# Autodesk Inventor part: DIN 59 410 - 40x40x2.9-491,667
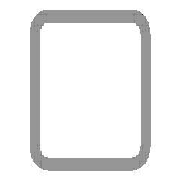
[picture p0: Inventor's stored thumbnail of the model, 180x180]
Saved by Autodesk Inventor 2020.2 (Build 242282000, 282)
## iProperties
Manager: www.cadconsulting.pl
Company: Fabian Stasiak CAD Consulting
_CCFamilyMember: 10
_CCFamilyDisplayName: DIN 59410 (Kwadrat) - Rurki stalowe o przekroju kwadratowym formowane na gorąco
_FrameMemberDoc: Frame Member File
_Version: 15.0.0
_GetPNFromCC: 1
Created: 2015-01
Part Number: DIN 59 410 - 40x40x2.9-491,667
Material: Stal, miękka
Description: Rurki stalowe o przekroju kwadratowym formowane na gorąco
Document SubType Name: Modellieren
Standard: DIN
Designer: F.Stasiak
Standards Organization: DIN
Language: pl-PL
Size Designation: 40x40x2.9
Categories: <MemberInstance><Categories><Category DisplayName="Kształtowniki konstrukcyjne" InternalName="089c4875-fa83-4c05-b084-43b9cc11f5ed" Mnemonic="GRDR"><CategoryPar
Stock Number: 40x40x2.9
Density: 7.85 g/cm^3
Appearance: Częściowo polerowana
Mass: 1443.74 g
Surface Area: 1280.31 cm^2
Volume: 183.916 cm^3
Catalog Web Link: www.expertbooks.pl
IsCustomPart: 1
G_W: 40,000 mm
G_H: 40,000 mm
G_L: 491,667 mm
+E51E7E97-BC58-461C-B30D-6957C6529D76+CUTDETAIL3: Wytnij
+E3496F03-4B02-4C0B-A602-6A17F15B3F21+CUTDETAIL4: Wytnij
Author: F.Stasiak
Subject: Zbiór ćwiczeń. Autodesk Inventor 2020. Kurs Professional
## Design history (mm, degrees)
node "Płaszczyzna początkowa"
node "Płaszczyzna końcowa"
sketch "Szkic"
  geometry: L1 (-14.2, 20)-(14.2, 20); L2 (20, 14.2)-(20, -14.2); L3 (14.2, -20)-(-14.2, -20); L4 (-20, -14.2)-(-20, 14.2); L5 (-29.682, 0)-(29.682, 0) reference; L6 (0, -29.682)-(0, 29.682) reference; L7 (-14.2, 17.1)-(14.2, 17.1); L8 (17.1, 14.2)-(17.1, -14.2); L9 (14.2, -17.1)-(-14.2, -17.1); L10 (-17.1, -14.2)-(-17.1, 14.2); A1 r 5.8 centre (-14.2, 14.2) between (-14.2, 20) and (-20, 14.2); A2 r 5.8 centre (14.2, 14.2) between (20, 14.2) and (14.2, 20); A3 r 5.8 centre (14.2, -14.2) between (14.2, -20) and (20, -14.2); A4 r 5.8 centre (-14.2, -14.2) between (-20, -14.2) and (-14.2, -20); A5 r 2.9 centre (-14.2, 14.2) between (-14.2, 17.1) and (-17.1, 14.2); A6 r 2.9 centre (14.2, 14.2) between (17.1, 14.2) and (14.2, 17.1); A7 r 2.9 centre (14.2, -14.2) between (14.2, -17.1) and (17.1, -14.2); A8 r 2.9 centre (-14.2, -14.2) between (-17.1, -14.2) and (-14.2, -17.1); 3 further points
  constraints: 16 end point, 16 point on circle, 8 centre point, 8 tangent, 6 point on line, 4 parallel, 3 equal radius, 3 perpendicular, 1 horizontal, 7 other
  dimensions: "b" = 40 distance of point (-20, 20) point (20, 20); "msp_r" = 5.8 radius of A1 (= 2 x ParT); "d8" = 20 distance between parallel lines of L4 L6 (= d9); "d9" = 20 distance between parallel lines of L3 L5 (= 0.5 x b); "d10" = 2.9 distance between parallel lines of L3 L9 (= ParT)
extrude "Bryła" new body sketch "Szkic" taper "d4" = 0 deg; stored distance "NLG" = 10
node "Driven Length"
  sketch "Sketch2"
    geometry: L1 (0, 0)-(10, 0) reference
    constraints: 2 end point, 1 horizontal
  workplane "Work Plane3"
  sketch "Sketch3"
    geometry: L1 (-2, 0)-(12, 0) reference; L2 (-2, 491.667)-(12, 491.667) reference
    dimensions: "d14" = 491.66667 distance between parallel lines of L1 L2 (derived)
node "Płaszczyzna konstrukcyjna6"
feature "Podział3"
node "Płaszczyzna konstrukcyjna7"
feature "Podział4"
body "Solid1"
other parameters: "ParT" = 2.9, "G_OFFSET_START" = 0 [user parameter; used in 1 equation term], "G_OFFSET_END" = -8.33333 [user parameter; used in 1 equation term], "d11" = 0 (computed from G_OFFSET_START), "d12" = 491.66667 (= G_OFFSET_END + B_L), "G_L" = 491.66667 (= d14) [user parameter], "d13" = 90 deg
